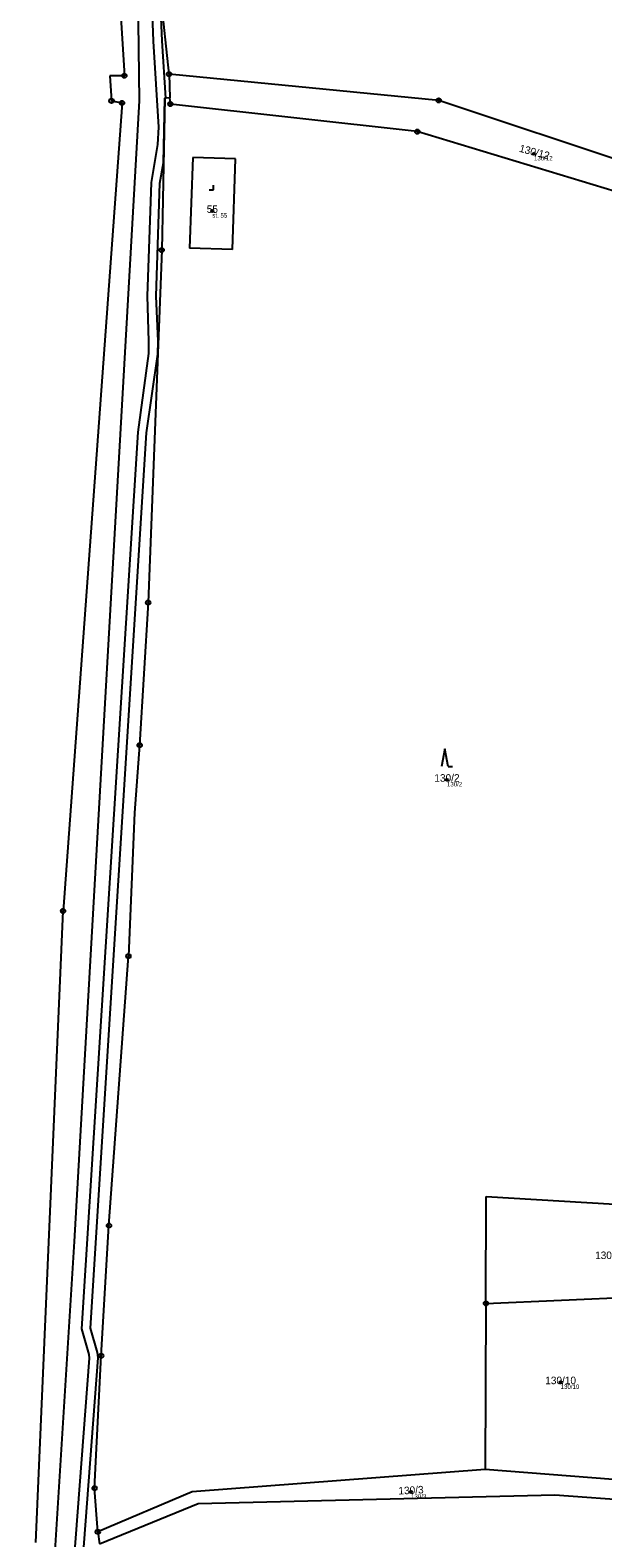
# Model space of a CAD drawing. Extents: x -867966 to -864255, y -1043242 to -1041327.
# Drawn here: x -866580 to -866450.7, y -1042687.4 to -1042347 of the extents above; entities that cross this region are included whole.
import ezdxf

# ---------------------------------------------------------------- set-up
doc = ezdxf.new("R2010")
doc.units = 0
for name, color, linetype in [('Definiční body', 7, 'Continuous'), ('Hranice parcel', 7, 'Continuous'), ('Parcelní čísla', 7, 'Continuous'), ('Poz předměty', 7, 'Continuous'), ('Věcná břemena k části', 7, 'Continuous'), ('Značky bodu BP', 7, 'Continuous'), ('Značky kultur', 7, 'Continuous')]:
    doc.layers.add(name, color=color, linetype=linetype)

msp = doc.modelspace()

# ---------------------------------------------------------------- linework, layer by layer
at = {"layer": 'Definiční body'}
for centre in [(-866466.21, -1042374.94), (-866538.83, -1042387.85), (-866485.86, -1042516.28), (-866460.2, -1042652.31), (-866493.96, -1042677.09)]:
    msp.add_circle(centre, 0.25, dxfattribs=at)
at = {"layer": 'Hranice parcel'}
for p, q in [((-866560, -1042335.78), (-866558.69, -1042357.31)), ((-866548.61, -1042356.95), (-866550.67, -1042337.21)), ((-866558.69, -1042357.31), (-866561.94, -1042357.34)), ((-866561.94, -1042357.34), (-866561.59, -1042362.98)), ((-866487.72, -1042362.88), (-866548.61, -1042356.95)), ((-866548.61, -1042356.95), (-866548.41, -1042362.3)), ((-866549.58, -1042362.36), (-866550.26, -1042396.68)), ((-866548.41, -1042362.3), (-866549.58, -1042362.36)), ((-866548.29, -1042363.7), (-866548.41, -1042362.3)), ((-866559.21, -1042363.46), (-866572.53, -1042545.9)), ((-866561.59, -1042362.98), (-866559.21, -1042363.46)), ((-866492.55, -1042369.94), (-866548.29, -1042363.7)), ((-866427.06, -1042383.14), (-866487.72, -1042362.88)), ((-866438.1, -1042386.41), (-866492.55, -1042369.94)), ((-866543.26, -1042375.75), (-866543.98, -1042396.24)), ((-866533.56, -1042376.09), (-866543.26, -1042375.75)), ((-866534.29, -1042396.58), (-866533.56, -1042376.09)), ((-866534.29, -1042396.58), (-866543.98, -1042396.24)), ((-866550.26, -1042396.68), (-866553.32, -1042476.27)), ((-866553.32, -1042476.27), (-866555.24, -1042508.47)), ((-866555.24, -1042508.47), (-866556.38, -1042523.76)), ((-866556.38, -1042523.76), (-866557.77, -1042556.11)), ((-866578.68, -1042688.47), (-866572.53, -1042545.9)), ((-866562.16, -1042616.92), (-866557.77, -1042556.11)), ((-866477.06, -1042634.49), (-866476.97, -1042610.38)), ((-866476.97, -1042610.38), (-866420.4, -1042613.68)), ((-866563.93, -1042646.31), (-866562.16, -1042616.92)), ((-866477.06, -1042634.49), (-866477.21, -1042672.03)), ((-866477.06, -1042634.49), (-866419.62, -1042632.04)), ((-866565.41, -1042676.22), (-866563.93, -1042646.31)), ((-866477.21, -1042672.03), (-866543.4, -1042677.06)), ((-866448.32, -1042674.24), (-866477.21, -1042672.03)), ((-866564.67, -1042686.07), (-866565.41, -1042676.22)), ((-866543.4, -1042677.06), (-866564.67, -1042686.07)), ((-866542, -1042679.69), (-866461.5, -1042677.71)), ((-866461.5, -1042677.71), (-866417.26, -1042681.02)), ((-866564.33, -1042688.78), (-866542, -1042679.69)), ((-866564.67, -1042686.07), (-866564.33, -1042688.78))]:
    msp.add_line(p, q, dxfattribs=at)
at = {"layer": 'Poz předměty'}
for p, q in [((-866555.28, -1042362.99), (-866555.69, -1042326.08)), ((-866569.94, -1042620.55), (-866555.28, -1042362.99)), ((-866579.96, -1042780.89), (-866569.94, -1042620.55))]:
    msp.add_line(p, q, dxfattribs=at)
at = {"layer": 'Věcná břemena k části'}
for points in [[(-866552.79, -1042333.51), (-866552.16, -1042349.51), (-866550.96, -1042368.94), (-866551.19, -1042372.87), (-866552.67, -1042381.4), (-866553.54, -1042407.08), (-866553.21, -1042417.23), (-866553.27, -1042420.04), (-866555.66, -1042437.78), (-866568.37, -1042640.23), (-866566.69, -1042646.03), (-866566.61, -1042646.85), (-866570.53, -1042698.38)], [(-866568.53, -1042698.52), (-866564.61, -1042646.81), (-866564.73, -1042645.59), (-866566.35, -1042640.05), (-866553.66, -1042437.96), (-866551.16, -1042420.2), (-866551.05, -1042417.22), (-866551.54, -1042407.08), (-866550.67, -1042381.6), (-866549.87, -1042377.01), (-866549.58, -1042362.36), (-866549.36, -1042362.35), (-866550.16, -1042349.41), (-866550.67, -1042337.21)]]:
    msp.add_lwpolyline(points, dxfattribs=at)
at = {"layer": 'Značky bodu BP'}
for centre, radius in [((-866558.69, -1042357.31), 0.5), ((-866558.69, -1042357.31), 0.0303), ((-866548.61, -1042356.95), 0.5), ((-866548.61, -1042356.95), 0.0303), ((-866561.59, -1042362.98), 0.5), ((-866487.72, -1042362.88), 0.5), ((-866561.59, -1042362.98), 0.0303), ((-866559.21, -1042363.46), 0.5), ((-866559.21, -1042363.46), 0.0303), ((-866548.29, -1042363.7), 0.5), ((-866548.29, -1042363.7), 0.0303), ((-866487.72, -1042362.88), 0.0303), ((-866492.55, -1042369.94), 0.5), ((-866492.55, -1042369.94), 0.0303), ((-866550.26, -1042396.68), 0.5), ((-866550.26, -1042396.68), 0.0303), ((-866553.32, -1042476.27), 0.5), ((-866553.32, -1042476.27), 0.0303), ((-866555.24, -1042508.47), 0.5), ((-866555.24, -1042508.47), 0.0303), ((-866572.53, -1042545.9), 0.5), ((-866572.53, -1042545.9), 0.0303), ((-866557.77, -1042556.11), 0.5), ((-866557.77, -1042556.11), 0.0303), ((-866562.16, -1042616.92), 0.5), ((-866562.16, -1042616.92), 0.0303), ((-866477.06, -1042634.49), 0.5), ((-866477.06, -1042634.49), 0.0303), ((-866563.93, -1042646.31), 0.5), ((-866563.93, -1042646.31), 0.0303), ((-866565.41, -1042676.22), 0.5), ((-866565.41, -1042676.22), 0.0303), ((-866564.67, -1042686.07), 0.5), ((-866564.67, -1042686.07), 0.0303)]:
    msp.add_circle(centre, radius, dxfattribs=at)
at = {"layer": 'Značky kultur'}
for p, q in [((-866538.55, -1042383.04), (-866538.55, -1042382.04)), ((-866539.55, -1042383.04), (-866538.55, -1042383.04)), ((-866486.32, -1042509.26), (-866487.07, -1042513.26)), ((-866485.57, -1042513.26), (-866486.32, -1042509.26)), ((-866485.57, -1042513.26), (-866484.57, -1042513.26))]:
    msp.add_line(p, q, dxfattribs=at)

# ---------------------------------------------------------------- texts
at = {"layer": 'Definiční body'}
for s, p in [('130/12', (-866466.21, -1042376.43)), ('st. 55', (-866538.83, -1042389.34)), ('130/2', (-866485.86, -1042517.77)), ('130/10', (-866460.2, -1042653.8)), ('130/3', (-866493.96, -1042678.58))]:
    msp.add_text(s, height=1, dxfattribs=at).set_placement(p)
at = {"layer": 'Parcelní čísla'}
for s, rotation, p in [('130/12', 345, (-866469.67, -1042374.45)), ('130/3', 3, (-866496.77, -1042677.66))]:
    msp.add_text(s, height=1.7, rotation=rotation, dxfattribs=at).set_placement(p)
for s, p in [('55', (-866540.09, -1042388.28)), ('130/2', (-866488.7, -1042516.71)), ('130/22', (-866452.41, -1042624.48)), ('130/10', (-866463.67, -1042652.73))]:
    msp.add_text(s, height=1.7, dxfattribs=at).set_placement(p)

doc.saveas('drawing.dxf')
